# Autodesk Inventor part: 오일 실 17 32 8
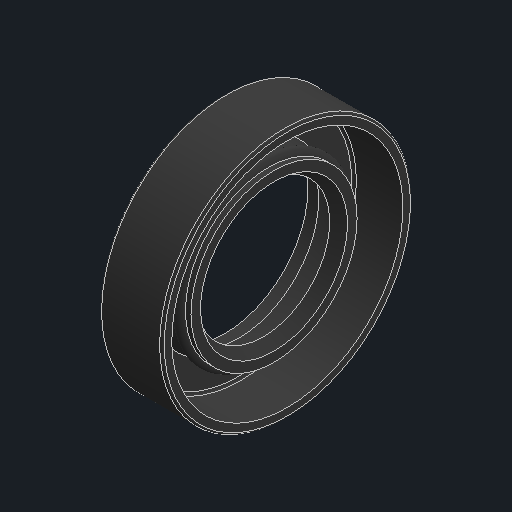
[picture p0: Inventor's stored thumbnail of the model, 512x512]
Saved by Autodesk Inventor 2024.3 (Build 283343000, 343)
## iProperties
Created: 2025-03
Part Number: 오일 실 17 32 8
Material: 고무
Description: 오일-실
Document SubType Name: Modeling
Designer: user
Density: 0.93 g/cm^3
Appearance: 기본값
Author: jhkim
Sending System: Autodesk Inventor 2025
Preprocessor: ST-DEVELOPER v20
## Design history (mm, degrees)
feature "Solid1"
node "솔리드1"
